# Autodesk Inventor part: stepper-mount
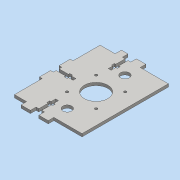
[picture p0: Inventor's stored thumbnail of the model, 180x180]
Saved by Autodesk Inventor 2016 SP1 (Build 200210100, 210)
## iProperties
Created: 2016-06
Part Number: stepper-mount
Material: Generic
Document SubType Name: Modeling
Designer: Mohamed A.
Density: 1 g/cm^3
Appearance: Default
Author: Mohamed A.
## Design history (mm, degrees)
sketch "Sketch1"
  geometry: L1 (-37.5, -49)-(37.5, -49); L2 (37.5, -49)-(37.5, 49); L3 (37.5, 49)-(-37.5, 49); L4 (-37.5, 49)-(-37.5, -49); L5 (-37.5, -49)-(37.5, 49); L6 (37.5, -49)-(-37.5, 49); 1 further point
  constraints: 12 end point, 2 midpoint, 2 parallel, 1 horizontal, 1 perpendicular
  dimensions: "d0" = 75 distance of L2.end L3.end; "d1" = 98 distance of L3.end L1.start
extrude "Extrusion1" new body sketch "Sketch1" distance "d2" = 3; taper "d3" = 0 deg
sketch "Sketch2"
  geometry: L1 (47.5, 46)-(-34.5, 46) reference; L2 (-34.5, -46)-(47.5, -46) reference; L3 (6.5, -46)-(6.5, 46); L4 (-14.5, 21)-(27.5, 21) reference; L5 (27.5, -21)-(-14.5, -21) reference; C1 r 1.5 at (22, -15.5) reference; C2 r 1.5 at (22, 15.5) reference; C3 r 1.5 at (-9, 15.5) reference; C4 r 1.5 at (-9, -15.5) reference; C5 r 12.5 at (6.5, 0) reference; C6 r 1.4 at (-9, -15.5); C7 r 1.4 at (-9, 15.5); C8 r 1.4 at (22, 15.5); C9 r 1.4 at (22, -15.5); C10 r 4.7 at (6.5, 30.7); C11 r 4.7 at (6.5, -30.7); 1 further point
  constraints: 6 centre point, 4 coincident, 3 midpoint, 2 end point, 2 point on line, 1 perpendicular
  dimensions: "d6" = 2.8 diameter of C6; "d7" = 2.8 diameter of C7; "d8" = 2.8 diameter of C8; "d9" = 2.8 diameter of C9; "d10" = 9.4 diameter of C10; "d13" = 9.4 diameter of C11; "d16" = 9.7 distance from line of L4 C10.centre (computed from d10); "d17" = 9.7 distance from line of C11.centre L5 (= d16)
extrude "Extrusion2" cut sketch "Sketch2" distance "d4" = 3; taper "d5" = 0 deg
sketch "Sketch3"
  geometry: L1 (-37.5, 49)-(-37.5, -49) reference; L2 (-37.5, 0)-(-11.464, 0); L3 (-37.5, 1.55)-(-16.5, 1.55); L4 (-16.5, 1.55)-(-16.5, -1.55); L5 (-16.5, -1.55)-(-37.5, -1.55); L6 (-37.5, -1.55)-(-37.5, 1.55); L7 (-24.5, 3)-(-21.5, 3); L8 (-21.5, 3)-(-21.5, -3); L9 (-21.5, -3)-(-24.5, -3); L10 (-24.5, -3)-(-24.5, 3); L11 (-37.5, 4.5)-(-34.5, 4.5); L12 (-34.5, 4.5)-(-34.5, -4.5); L13 (-34.5, -4.5)-(-37.5, -4.5); L14 (-37.5, -4.5)-(-37.5, 4.5); L15 (-4.005, 33)-(-10.005, 33); L16 (-10.005, 33)-(-10.005, 36); L17 (-4.005, 36)-(-4.005, 33); L18 (-10.005, 36)-(-4.005, 36); L19 (-7.005, 48.589)-(-7.005, 22.553); L20 (-5.455, 49)-(-5.455, 28); L21 (-8.555, 28)-(-8.555, 49); L22 (-11.505, 46)-(-11.505, 49); L23 (-2.505, 49)-(-2.505, 46); L24 (-2.505, 46)-(-11.505, 46); L25 (-5.455, 28)-(-8.555, 28); L26 (-11.505, 49)-(-2.505, 49); L27 (-8.555, 49)-(-5.455, 49); L28 (37.5, 49)-(-37.5, 49) reference; L29 (-10.005, -33)-(-10.005, -36); L30 (-11.505, -46)-(-11.505, -49); L31 (-8.555, -28)-(-8.555, -49); L32 (-7.005, -48.589)-(-7.005, -22.553); L33 (-5.455, -28)-(-8.555, -28); L34 (-8.555, -49)-(-5.455, -49); L35 (-5.455, -49)-(-5.455, -28); L36 (-4.005, -33)-(-10.005, -33); L37 (-4.005, -36)-(-4.005, -33); L38 (-10.005, -36)-(-4.005, -36); L39 (-2.505, -46)-(-11.505, -46); L40 (-2.505, -49)-(-2.505, -46); L41 (-11.505, -49)-(-2.505, -49); L42 (-37.5, 49)-(-34.5, 49); L43 (-34.5, 49)-(-34.5, 16.333); L44 (-34.5, 16.333)-(-37.5, 16.333); L45 (-37.5, 16.333)-(-37.5, 49); L46 (-37.5, -49)-(-34.5, -49); L47 (-34.5, -49)-(-34.5, -16.333); L48 (-34.5, -16.333)-(-37.5, -16.333); L49 (-37.5, -16.333)-(-37.5, -49); L50 (-34.5, -49)-(-21.505, -49); L51 (-21.505, -49)-(-21.505, -46); L52 (-21.505, -46)-(-34.5, -46); L53 (-34.5, -46)-(-34.5, -49); L54 (-37.5, -49)-(37.5, -49) reference; L55 (37.5, -49)-(7.495, -49); L56 (7.495, -49)-(7.495, -46); L57 (7.495, -46)-(37.5, -46); L58 (37.5, -46)-(37.5, -49); L59 (37.5, 49)-(7.495, 49); L60 (7.495, 49)-(7.495, 46); L61 (7.495, 46)-(37.5, 46); L62 (37.5, 46)-(37.5, 49); L63 (-34.5, 49)-(-18.555, 49); L64 (-18.555, 49)-(-18.555, 45.295)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; 1 further point
  constraints: 126 end point, 24 parallel, 14 symmetric about line, 12 perpendicular, 10 horizontal, 5 point on line, 2 collinear, 1 midpoint, 6 other
  dimensions: "d18" = 21 distance of L4.end L5.end; "d19" = 3.1 distance of L3.end L4.end; "d20" = 3 distance of L8.end L9.end; "d21" = 6 distance of L7.end L8.end; "d22" = 5 distance between parallel lines of L8 L4; "d23" = 3 distance between parallel lines of L14 L12; "d24" = 9 distance between parallel lines of L13 L11; "d25" = 21 distance of L21.start L21.end; "d26" = 3.1 distance of L20.end L21.start; "d27" = 3 distance of L15.end L16.end; "d28" = 6 distance of L15.start L15.end; "d29" = 5 distance between parallel lines of L15 L25; "d30" = 3 distance between parallel lines of L26 L24; "d31" = 9 distance between parallel lines of L22 L23; "d34" = 98 distance between parallel lines of L54 L28 (derived); "d35" = 32.66667 distance between parallel lines of L28 L44 (= 0.333333 x d34); "d36" = 32.66667 distance between parallel lines of L54 L48 (= d35); "d37" = 10 distance between parallel lines of L21 L64; "d38" = 10 distance between parallel lines of L23 L60; "d39" = 10 distance between parallel lines of L51 L30 (= d37); "d40" = 10 distance between parallel lines of L40 L56 (derived)
extrude "Extrusion3" cut sketch "Sketch3" distance "d32" = 3; taper "d33" = 0 deg
sketch "Sketch4"
  geometry: L1 (0, 3)-(0, 0) reference; L2 (0, 0)-(10, 0) reference; L3 (10, 0)-(10, 3) reference; L4 (0, 3)-(10, 3) reference; L5 (-9, 0)-(-9, 3) reference; L6 (-19, 3)-(-9, 3) reference; L7 (-19, 3)-(-19, 0) reference; L8 (-19, 0)-(-9, 0) reference; 1 further point
extrude "Extrusion4" join sketch "Sketch4" distance "d41" = 3; taper "d42" = 0 deg
sketch "Sketch5"
  geometry: L1 (0, 0)-(0, -3) reference; L2 (7.05, -3)-(0, -3) reference; L3 (7.05, -3)-(7.05, 0) reference; L4 (7.05, 0)-(0, 0) reference; L5 (26.05, -3)-(26.05, 0) reference; L6 (26.05, 0)-(16.05, 0) reference; L7 (16.05, 0)-(16.05, -3) reference; L8 (26.05, -3)-(16.05, -3) reference; 1 further point
extrude "Extrusion5" join sketch "Sketch5" distance "d43" = 3; taper "d44" = 0 deg
body "Solid1"
node "Reference1"
node "Reference2"
node "Reference3"
node "Reference4"
node "Reference5"
node "Reference8"
node "Reference9"
node "Reference10"
node "Reference11"
node "Projected Loop1"
node "Projected Loop2"
node "Projected Loop3"
node "Projected Loop4"
